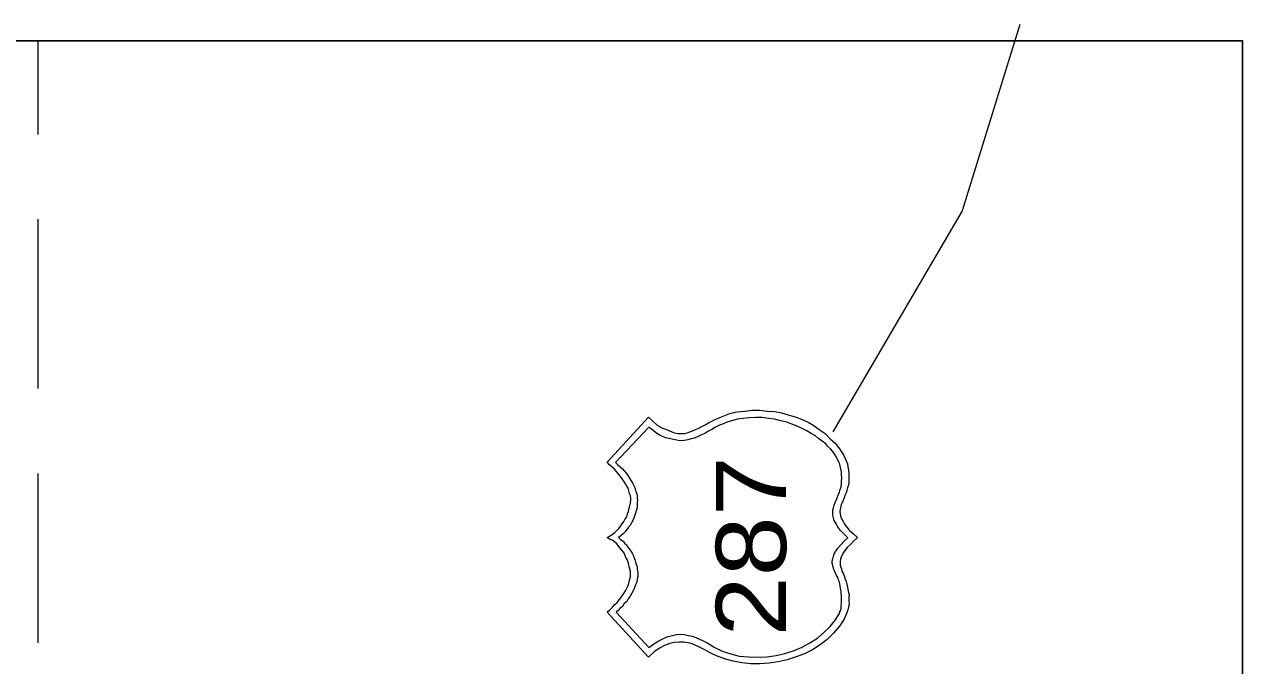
# Model space of a CAD drawing. Extents: x 2363323 to 2367082, y 6956018 to 6980837.
# Drawn here: x 2366130.8 to 2366219.2, y 6980790.2 to 6980836.7 of the extents above; entities that cross this region are included whole.
import ezdxf

# ---------------------------------------------------------------- set-up
doc = ezdxf.new("R2010")
doc.units = 0
doc.header["$LTSCALE"] = 4.1
doc.linetypes.add('MEDIUM_DASHED', pattern=[4.5, 3, -1.5])
doc.layers.add('62', color=7, linetype='Continuous', lineweight=13)
doc.layers.add('63', color=7, linetype='Continuous', lineweight=13)

msp = doc.modelspace()

# ---------------------------------------------------------------- linework, layer by layer
at = {"layer": '62'}
for p, q in [((2366203.073, 6980836.74), (2366198.884, 6980823.214)), ((2366198.884, 6980823.214), (2366189.502, 6980807.17))]:
    msp.add_line(p, q, dxfattribs=at)
at = {"layer": '62', "linetype": 'MEDIUM_DASHED'}
msp.add_line((2366131.806, 6980385.954), (2366131.805, 6980835.548), dxfattribs=at)
at = {"layer": '62', "lineweight": 25}
msp.add_lwpolyline([(2365753.976, 6980385.954), (2366219.249, 6980385.954), (2366219.249, 6980835.546), (2365753.974, 6980835.546)], dxfattribs=at)
at = {"layer": '62'}
for points in [[(2366176.114, 6980790.813), (2366173.121, 6980794.074), (2366173.301, 6980794.256), (2366173.504, 6980794.434), (2366173.661, 6980794.636), (2366173.842, 6980794.794), (2366173.998, 6980795), (2366174.135, 6980795.178), (2366174.268, 6980795.358), (2366174.404, 6980795.56), (2366174.495, 6980795.718), (2366174.584, 6980795.92), (2366174.675, 6980796.1), (2366174.72, 6980796.303), (2366174.765, 6980796.483), (2366174.807, 6980796.64), (2366174.81, 6980796.866), (2366174.81, 6980797.068), (2366174.764, 6980797.203), (2366174.718, 6980797.36), (2366174.696, 6980797.54), (2366174.628, 6980797.719), (2366174.561, 6980797.902), (2366174.471, 6980798.058), (2366174.404, 6980798.24), (2366174.315, 6980798.418), (2366174.18, 6980798.576), (2366174.045, 6980798.756), (2366173.91, 6980798.913), (2366173.798, 6980799.07), (2366173.638, 6980799.183), (2366173.482, 6980799.318), (2366173.28, 6980799.386), (2366173.122, 6980799.498), (2366173.278, 6980799.61), (2366173.481, 6980799.723), (2366173.661, 6980799.858), (2366173.798, 6980799.993), (2366173.955, 6980800.152), (2366174.09, 6980800.33), (2366174.201, 6980800.488), (2366174.315, 6980800.668), (2366174.426, 6980800.846), (2366174.538, 6980801.006), (2366174.585, 6980801.23), (2366174.674, 6980801.39), (2366174.72, 6980801.636), (2366174.764, 6980801.793), (2366174.81, 6980802.018), (2366174.832, 6980802.2), (2366174.831, 6980802.356), (2366174.808, 6980802.558), (2366174.742, 6980802.693), (2366174.698, 6980802.894), (2366174.628, 6980803.076), (2366174.538, 6980803.234), (2366174.45, 6980803.392), (2366174.336, 6980803.593), (2366174.201, 6980803.752), (2366174.09, 6980803.93), (2366173.931, 6980804.088), (2366173.796, 6980804.29), (2366173.64, 6980804.45), (2366173.458, 6980804.628), (2366173.278, 6980804.786), (2366173.121, 6980804.966), (2366176.114, 6980808.23), (2366176.43, 6980807.936), (2366176.744, 6980807.644), (2366177.126, 6980807.44), (2366177.531, 6980807.284), (2366177.915, 6980807.126), (2366178.252, 6980807.056), (2366178.544, 6980807.058), (2366178.746, 6980807.058), (2366178.928, 6980807.103), (2366179.128, 6980807.172), (2366179.31, 6980807.238), (2366179.534, 6980807.328), (2366179.758, 6980807.44), (2366179.984, 6980807.553), (2366180.231, 6980807.69), (2366180.478, 6980807.823), (2366180.75, 6980807.958), (2366180.996, 6980808.093), (2366181.29, 6980808.206), (2366181.538, 6980808.318), (2366181.785, 6980808.408), (2366182.031, 6980808.498), (2366182.302, 6980808.566), (2366182.548, 6980808.61), (2366183.112, 6980808.678), (2366183.675, 6980808.747), (2366184.192, 6980808.746), (2366184.731, 6980808.678), (2366185.271, 6980808.634), (2366185.768, 6980808.543), (2366186.262, 6980808.408), (2366186.756, 6980808.25), (2366187.228, 6980808.093), (2366187.702, 6980807.868)], [(2366188.466, 6980806.676), (2366188.242, 6980806.878), (2366187.926, 6980807.06), (2366187.612, 6980807.238), (2366187.274, 6980807.418), (2366186.915, 6980807.576), (2366186.532, 6980807.734), (2366186.15, 6980807.87), (2366185.721, 6980807.98), (2366185.272, 6980808.093), (2366184.844, 6980808.138), (2366184.372, 6980808.204), (2366183.898, 6980808.207), (2366183.405, 6980808.183), (2366182.976, 6980808.138), (2366182.572, 6980808.093), (2366182.235, 6980807.982), (2366181.875, 6980807.89), (2366181.558, 6980807.756), (2366181.266, 6980807.643), (2366180.974, 6980807.508), (2366180.705, 6980807.35), (2366180.434, 6980807.194), (2366180.208, 6980807.058), (2366179.961, 6980806.946), (2366179.714, 6980806.833), (2366179.445, 6980806.72), (2366179.22, 6980806.653), (2366178.971, 6980806.586), (2366178.701, 6980806.54), (2366178.386, 6980806.518), (2366178.048, 6980806.586), (2366177.711, 6980806.653), (2366177.374, 6980806.743), (2366177.015, 6980806.878), (2366176.721, 6980807.058), (2366176.428, 6980807.284), (2366176.136, 6980807.508), (2366173.728, 6980804.943), (2366173.886, 6980804.787), (2366174.045, 6980804.65), (2366174.224, 6980804.493), (2366174.36, 6980804.336), (2366174.516, 6980804.157), (2366174.628, 6980803.976), (2366174.741, 6980803.797), (2366174.854, 6980803.616), (2366174.966, 6980803.413), (2366175.078, 6980803.233), (2366175.146, 6980803.03), (2366175.191, 6980802.852), (2366175.26, 6980802.67), (2366175.281, 6980802.513), (2366175.304, 6980802.357), (2366175.328, 6980802.198), (2366175.304, 6980802.042), (2366175.281, 6980801.86), (2366175.282, 6980801.66), (2366175.236, 6980801.5), (2366175.168, 6980801.276), (2366175.124, 6980801.118), (2366175.056, 6980800.938), (2366174.968, 6980800.736), (2366174.876, 6980800.578), (2366174.786, 6980800.376), (2366174.675, 6980800.242), (2366174.538, 6980800.083), (2366174.426, 6980799.904), (2366174.268, 6980799.77), (2366174.112, 6980799.634), (2366173.931, 6980799.5), (2366174.088, 6980799.363), (2366174.268, 6980799.23), (2366174.381, 6980799.093), (2366174.516, 6980798.958), (2366174.606, 6980798.802), (2366174.718, 6980798.688), (2366174.832, 6980798.508), (2366174.921, 6980798.373), (2366174.99, 6980798.216), (2366175.08, 6980798.036), (2366175.125, 6980797.9), (2366175.168, 6980797.722), (2366175.214, 6980797.563), (2366175.282, 6980797.406), (2366175.281, 6980797.226), (2366175.326, 6980797.07), (2366175.35, 6980796.91), (2366175.348, 6980796.686), (2366175.281, 6980796.483), (2366175.258, 6980796.258), (2366175.168, 6980796.078), (2366175.102, 6980795.852), (2366175.011, 6980795.63), (2366174.898, 6980795.47), (2366174.786, 6980795.246), (2366174.651, 6980795.043), (2366174.538, 6980794.863), (2366174.357, 6980794.704), (2366174.224, 6980794.503), (2366174.044, 6980794.344)], [(2366187.702, 6980807.868), (2366188.128, 6980807.62), (2366188.511, 6980807.328), (2366188.94, 6980807.058), (2366189.298, 6980806.674), (2366189.66, 6980806.338), (2366189.975, 6980805.933), (2366190.132, 6980805.708), (2366190.266, 6980805.507), (2366190.378, 6980805.28), (2366190.468, 6980805.056), (2366190.56, 6980804.853), (2366190.581, 6980804.628), (2366190.628, 6980804.38), (2366190.671, 6980804.18), (2366190.671, 6980803.93), (2366190.671, 6980803.704), (2366190.648, 6980803.503), (2366190.626, 6980803.323), (2366190.558, 6980803.1), (2366190.514, 6980802.918), (2366190.47, 6980802.738), (2366190.378, 6980802.558), (2366190.311, 6980802.38), (2366190.245, 6980802.198), (2366190.176, 6980802.063), (2366190.11, 6980801.883), (2366190.086, 6980801.748), (2366190.041, 6980801.568), (2366189.996, 6980801.39), (2366190.02, 6980801.23), (2366190.065, 6980801.05), (2366190.131, 6980800.848), (2366190.244, 6980800.668), (2366190.356, 6980800.466), (2366190.514, 6980800.24), (2366190.716, 6980800.016), (2366190.986, 6980799.768), (2366191.278, 6980799.498), (2366191.008, 6980799.226), (2366190.784, 6980799.003), (2366190.558, 6980798.8), (2366190.401, 6980798.576), (2366190.268, 6980798.418), (2366190.178, 6980798.238), (2366190.108, 6980798.08), (2366190.065, 6980797.923), (2366190.041, 6980797.788), (2366190.042, 6980797.63), (2366190.042, 6980797.496), (2366190.086, 6980797.34), (2366190.131, 6980797.227), (2366190.154, 6980797.068), (2366190.244, 6980796.912), (2366190.288, 6980796.776), (2366190.356, 6980796.642), (2366190.402, 6980796.483), (2366190.468, 6980796.303), (2366190.514, 6980796.1), (2366190.558, 6980795.92), (2366190.581, 6980795.718), (2366190.628, 6980795.516), (2366190.672, 6980795.337), (2366190.671, 6980795.112), (2366190.671, 6980794.908), (2366190.672, 6980794.704), (2366190.628, 6980794.458), (2366190.582, 6980794.254), (2366190.514, 6980794.029), (2366190.424, 6980793.806), (2366190.311, 6980793.579), (2366189.974, 6980793.062), (2366189.546, 6980792.565), (2366189.096, 6980792.094), (2366188.578, 6980791.712), (2366188.018, 6980791.352), (2366187.431, 6980791.06), (2366186.824, 6980790.836), (2366186.171, 6980790.632), (2366185.52, 6980790.474), (2366184.866, 6980790.384), (2366184.191, 6980790.339), (2366183.538, 6980790.338), (2366182.884, 6980790.406), (2366182.258, 6980790.519), (2366181.626, 6980790.699), (2366181.064, 6980790.924), (2366180.838, 6980791.014), (2366180.591, 6980791.126), (2366180.366, 6980791.262), (2366180.098, 6980791.396), (2366179.828, 6980791.533), (2366179.558, 6980791.666), (2366179.286, 6980791.78), (2366178.995, 6980791.846), (2366178.68, 6980791.914), (2366178.341, 6980791.916), (2366178.005, 6980791.892), (2366177.666, 6980791.802), (2366177.284, 6980791.668), (2366176.902, 6980791.464)], [(2366173.774, 6980794.076), (2366176.136, 6980791.509), (2366176.498, 6980791.779), (2366176.858, 6980792.004), (2366177.194, 6980792.162), (2366177.508, 6980792.319), (2366177.846, 6980792.386), (2366178.138, 6980792.454), (2366178.408, 6980792.476), (2366178.724, 6980792.456), (2366179.018, 6980792.388), (2366179.286, 6980792.342), (2366179.558, 6980792.252), (2366179.828, 6980792.116), (2366180.096, 6980792.006), (2366180.366, 6980791.869), (2366180.615, 6980791.713), (2366180.884, 6980791.554), (2366181.468, 6980791.262), (2366182.1, 6980791.06), (2366182.706, 6980790.902), (2366183.381, 6980790.834), (2366184.034, 6980790.812), (2366184.708, 6980790.834), (2366185.384, 6980790.946), (2366186.014, 6980791.082), (2366186.644, 6980791.284), (2366187.274, 6980791.554), (2366187.838, 6980791.869), (2366188.378, 6980792.208), (2366188.848, 6980792.612), (2366189.298, 6980793.039), (2366189.66, 6980793.512), (2366189.974, 6980793.984), (2366190.018, 6980794.096), (2366190.088, 6980794.232), (2366190.108, 6980794.389), (2366190.108, 6980794.569), (2366190.131, 6980794.704), (2366190.132, 6980794.886), (2366190.132, 6980795.066), (2366190.132, 6980795.246), (2366190.11, 6980795.448), (2366190.108, 6980795.606), (2366190.065, 6980795.806), (2366190.041, 6980795.988), (2366189.998, 6980796.146), (2366189.952, 6980796.326), (2366189.884, 6980796.483), (2366189.861, 6980796.618), (2366189.772, 6980796.753), (2366189.702, 6980796.91), (2366189.638, 6980797.023), (2366189.568, 6980797.179), (2366189.524, 6980797.338), (2366189.502, 6980797.473), (2366189.458, 6980797.63), (2366189.456, 6980797.788), (2366189.501, 6980797.946), (2366189.546, 6980798.15), (2366189.591, 6980798.328), (2366189.726, 6980798.506), (2366189.861, 6980798.734), (2366190.086, 6980798.958), (2366190.311, 6980799.228), (2366190.582, 6980799.476), (2366190.288, 6980799.768), (2366190.041, 6980800.038), (2366189.862, 6980800.284), (2366189.704, 6980800.533), (2366189.591, 6980800.736), (2366189.546, 6980800.938), (2366189.501, 6980801.118), (2366189.501, 6980801.343), (2366189.501, 6980801.502), (2366189.546, 6980801.658), (2366189.591, 6980801.86), (2366189.658, 6980802.04), (2366189.748, 6980802.2), (2366189.814, 6980802.378), (2366189.885, 6980802.58), (2366189.975, 6980802.783), (2366190.042, 6980802.986), (2366190.108, 6980803.186), (2366190.132, 6980803.39), (2366190.131, 6980803.616), (2366190.154, 6980803.82), (2366190.132, 6980804.044), (2366190.131, 6980804.246), (2366190.086, 6980804.469), (2366190.042, 6980804.696), (2366189.974, 6980804.898), (2366189.862, 6980805.124), (2366189.771, 6980805.326), (2366189.636, 6980805.528), (2366189.502, 6980805.753), (2366189.321, 6980805.933), (2366189.118, 6980806.136), (2366188.962, 6980806.316), (2366188.714, 6980806.496), (2366188.466, 6980806.676)], [(2366174.044, 6980794.344), (2366173.91, 6980794.209), (2366173.774, 6980794.076)], [(2366176.902, 6980791.464), (2366176.52, 6980791.194), (2366176.114, 6980790.813)]]:
    msp.add_lwpolyline(points, dxfattribs=at)
at = {"layer": '63'}
for p, q in [((2366203.073, 6980836.74), (2366198.884, 6980823.214)), ((2366198.884, 6980823.214), (2366189.502, 6980807.17))]:
    msp.add_line(p, q, dxfattribs=at)
at = {"layer": '63', "linetype": 'MEDIUM_DASHED'}
msp.add_line((2366131.806, 6980385.954), (2366131.805, 6980835.548), dxfattribs=at)
at = {"layer": '63', "lineweight": 25}
msp.add_lwpolyline([(2365753.976, 6980385.954), (2366219.249, 6980385.954), (2366219.249, 6980835.546), (2365753.974, 6980835.546)], dxfattribs=at)
at = {"layer": '63'}
for points in [[(2366176.114, 6980790.813), (2366173.121, 6980794.074), (2366173.301, 6980794.256), (2366173.504, 6980794.434), (2366173.661, 6980794.636), (2366173.842, 6980794.794), (2366173.998, 6980795), (2366174.135, 6980795.178), (2366174.268, 6980795.358), (2366174.404, 6980795.56), (2366174.495, 6980795.718), (2366174.584, 6980795.92), (2366174.675, 6980796.1), (2366174.72, 6980796.303), (2366174.765, 6980796.483), (2366174.807, 6980796.64), (2366174.81, 6980796.866), (2366174.81, 6980797.068), (2366174.764, 6980797.203), (2366174.718, 6980797.36), (2366174.696, 6980797.54), (2366174.628, 6980797.719), (2366174.561, 6980797.902), (2366174.471, 6980798.058), (2366174.404, 6980798.24), (2366174.315, 6980798.418), (2366174.18, 6980798.576), (2366174.045, 6980798.756), (2366173.91, 6980798.913), (2366173.798, 6980799.07), (2366173.638, 6980799.183), (2366173.482, 6980799.318), (2366173.28, 6980799.386), (2366173.122, 6980799.498), (2366173.278, 6980799.61), (2366173.481, 6980799.723), (2366173.661, 6980799.858), (2366173.798, 6980799.993), (2366173.955, 6980800.152), (2366174.09, 6980800.33), (2366174.201, 6980800.488), (2366174.315, 6980800.668), (2366174.426, 6980800.846), (2366174.538, 6980801.006), (2366174.585, 6980801.23), (2366174.674, 6980801.39), (2366174.72, 6980801.636), (2366174.764, 6980801.793), (2366174.81, 6980802.018), (2366174.832, 6980802.2), (2366174.831, 6980802.356), (2366174.808, 6980802.558), (2366174.742, 6980802.693), (2366174.698, 6980802.894), (2366174.628, 6980803.076), (2366174.538, 6980803.234), (2366174.45, 6980803.392), (2366174.336, 6980803.593), (2366174.201, 6980803.752), (2366174.09, 6980803.93), (2366173.931, 6980804.088), (2366173.796, 6980804.29), (2366173.64, 6980804.45), (2366173.458, 6980804.628), (2366173.278, 6980804.786), (2366173.121, 6980804.966), (2366176.114, 6980808.23), (2366176.43, 6980807.936), (2366176.744, 6980807.644), (2366177.126, 6980807.44), (2366177.531, 6980807.284), (2366177.915, 6980807.126), (2366178.252, 6980807.056), (2366178.544, 6980807.058), (2366178.746, 6980807.058), (2366178.928, 6980807.103), (2366179.128, 6980807.172), (2366179.31, 6980807.238), (2366179.534, 6980807.328), (2366179.758, 6980807.44), (2366179.984, 6980807.553), (2366180.231, 6980807.69), (2366180.478, 6980807.823), (2366180.75, 6980807.958), (2366180.996, 6980808.093), (2366181.29, 6980808.206), (2366181.538, 6980808.318), (2366181.785, 6980808.408), (2366182.031, 6980808.498), (2366182.302, 6980808.566), (2366182.548, 6980808.61), (2366183.112, 6980808.678), (2366183.675, 6980808.747), (2366184.192, 6980808.746), (2366184.731, 6980808.678), (2366185.271, 6980808.634), (2366185.768, 6980808.543), (2366186.262, 6980808.408), (2366186.756, 6980808.25), (2366187.228, 6980808.093), (2366187.702, 6980807.868)], [(2366188.466, 6980806.676), (2366188.242, 6980806.878), (2366187.926, 6980807.06), (2366187.612, 6980807.238), (2366187.274, 6980807.418), (2366186.915, 6980807.576), (2366186.532, 6980807.734), (2366186.15, 6980807.87), (2366185.721, 6980807.98), (2366185.272, 6980808.093), (2366184.844, 6980808.138), (2366184.372, 6980808.204), (2366183.898, 6980808.207), (2366183.405, 6980808.183), (2366182.976, 6980808.138), (2366182.572, 6980808.093), (2366182.235, 6980807.982), (2366181.875, 6980807.89), (2366181.558, 6980807.756), (2366181.266, 6980807.643), (2366180.974, 6980807.508), (2366180.705, 6980807.35), (2366180.434, 6980807.194), (2366180.208, 6980807.058), (2366179.961, 6980806.946), (2366179.714, 6980806.833), (2366179.445, 6980806.72), (2366179.22, 6980806.653), (2366178.971, 6980806.586), (2366178.701, 6980806.54), (2366178.386, 6980806.518), (2366178.048, 6980806.586), (2366177.711, 6980806.653), (2366177.374, 6980806.743), (2366177.015, 6980806.878), (2366176.721, 6980807.058), (2366176.428, 6980807.284), (2366176.136, 6980807.508), (2366173.728, 6980804.943), (2366173.886, 6980804.787), (2366174.045, 6980804.65), (2366174.224, 6980804.493), (2366174.36, 6980804.336), (2366174.516, 6980804.157), (2366174.628, 6980803.976), (2366174.741, 6980803.797), (2366174.854, 6980803.616), (2366174.966, 6980803.413), (2366175.078, 6980803.233), (2366175.146, 6980803.03), (2366175.191, 6980802.852), (2366175.26, 6980802.67), (2366175.281, 6980802.513), (2366175.304, 6980802.357), (2366175.328, 6980802.198), (2366175.304, 6980802.042), (2366175.281, 6980801.86), (2366175.282, 6980801.66), (2366175.236, 6980801.5), (2366175.168, 6980801.276), (2366175.124, 6980801.118), (2366175.056, 6980800.938), (2366174.968, 6980800.736), (2366174.876, 6980800.578), (2366174.786, 6980800.376), (2366174.675, 6980800.242), (2366174.538, 6980800.083), (2366174.426, 6980799.904), (2366174.268, 6980799.77), (2366174.112, 6980799.634), (2366173.931, 6980799.5), (2366174.088, 6980799.363), (2366174.268, 6980799.23), (2366174.381, 6980799.093), (2366174.516, 6980798.958), (2366174.606, 6980798.802), (2366174.718, 6980798.688), (2366174.832, 6980798.508), (2366174.921, 6980798.373), (2366174.99, 6980798.216), (2366175.08, 6980798.036), (2366175.125, 6980797.9), (2366175.168, 6980797.722), (2366175.214, 6980797.563), (2366175.282, 6980797.406), (2366175.281, 6980797.226), (2366175.326, 6980797.07), (2366175.35, 6980796.91), (2366175.348, 6980796.686), (2366175.281, 6980796.483), (2366175.258, 6980796.258), (2366175.168, 6980796.078), (2366175.102, 6980795.852), (2366175.011, 6980795.63), (2366174.898, 6980795.47), (2366174.786, 6980795.246), (2366174.651, 6980795.043), (2366174.538, 6980794.863), (2366174.357, 6980794.704), (2366174.224, 6980794.503), (2366174.044, 6980794.344)], [(2366187.702, 6980807.868), (2366188.128, 6980807.62), (2366188.511, 6980807.328), (2366188.94, 6980807.058), (2366189.298, 6980806.674), (2366189.66, 6980806.338), (2366189.975, 6980805.933), (2366190.132, 6980805.708), (2366190.266, 6980805.507), (2366190.378, 6980805.28), (2366190.468, 6980805.056), (2366190.56, 6980804.853), (2366190.581, 6980804.628), (2366190.628, 6980804.38), (2366190.671, 6980804.18), (2366190.671, 6980803.93), (2366190.671, 6980803.704), (2366190.648, 6980803.503), (2366190.626, 6980803.323), (2366190.558, 6980803.1), (2366190.514, 6980802.918), (2366190.47, 6980802.738), (2366190.378, 6980802.558), (2366190.311, 6980802.38), (2366190.245, 6980802.198), (2366190.176, 6980802.063), (2366190.11, 6980801.883), (2366190.086, 6980801.748), (2366190.041, 6980801.568), (2366189.996, 6980801.39), (2366190.02, 6980801.23), (2366190.065, 6980801.05), (2366190.131, 6980800.848), (2366190.244, 6980800.668), (2366190.356, 6980800.466), (2366190.514, 6980800.24), (2366190.716, 6980800.016), (2366190.986, 6980799.768), (2366191.278, 6980799.498), (2366191.008, 6980799.226), (2366190.784, 6980799.003), (2366190.558, 6980798.8), (2366190.401, 6980798.576), (2366190.268, 6980798.418), (2366190.178, 6980798.238), (2366190.108, 6980798.08), (2366190.065, 6980797.923), (2366190.041, 6980797.788), (2366190.042, 6980797.63), (2366190.042, 6980797.496), (2366190.086, 6980797.34), (2366190.131, 6980797.227), (2366190.154, 6980797.068), (2366190.244, 6980796.912), (2366190.288, 6980796.776), (2366190.356, 6980796.642), (2366190.402, 6980796.483), (2366190.468, 6980796.303), (2366190.514, 6980796.1), (2366190.558, 6980795.92), (2366190.581, 6980795.718), (2366190.628, 6980795.516), (2366190.672, 6980795.337), (2366190.671, 6980795.112), (2366190.671, 6980794.908), (2366190.672, 6980794.704), (2366190.628, 6980794.458), (2366190.582, 6980794.254), (2366190.514, 6980794.029), (2366190.424, 6980793.806), (2366190.311, 6980793.579), (2366189.974, 6980793.062), (2366189.546, 6980792.565), (2366189.096, 6980792.094), (2366188.578, 6980791.712), (2366188.018, 6980791.352), (2366187.431, 6980791.06), (2366186.824, 6980790.836), (2366186.171, 6980790.632), (2366185.52, 6980790.474), (2366184.866, 6980790.384), (2366184.191, 6980790.339), (2366183.538, 6980790.338), (2366182.884, 6980790.406), (2366182.258, 6980790.519), (2366181.626, 6980790.699), (2366181.064, 6980790.924), (2366180.838, 6980791.014), (2366180.591, 6980791.126), (2366180.366, 6980791.262), (2366180.098, 6980791.396), (2366179.828, 6980791.533), (2366179.558, 6980791.666), (2366179.286, 6980791.78), (2366178.995, 6980791.846), (2366178.68, 6980791.914), (2366178.341, 6980791.916), (2366178.005, 6980791.892), (2366177.666, 6980791.802), (2366177.284, 6980791.668), (2366176.902, 6980791.464)], [(2366173.774, 6980794.076), (2366176.136, 6980791.509), (2366176.498, 6980791.779), (2366176.858, 6980792.004), (2366177.194, 6980792.162), (2366177.508, 6980792.319), (2366177.846, 6980792.386), (2366178.138, 6980792.454), (2366178.408, 6980792.476), (2366178.724, 6980792.456), (2366179.018, 6980792.388), (2366179.286, 6980792.342), (2366179.558, 6980792.252), (2366179.828, 6980792.116), (2366180.096, 6980792.006), (2366180.366, 6980791.869), (2366180.615, 6980791.713), (2366180.884, 6980791.554), (2366181.468, 6980791.262), (2366182.1, 6980791.06), (2366182.706, 6980790.902), (2366183.381, 6980790.834), (2366184.034, 6980790.812), (2366184.708, 6980790.834), (2366185.384, 6980790.946), (2366186.014, 6980791.082), (2366186.644, 6980791.284), (2366187.274, 6980791.554), (2366187.838, 6980791.869), (2366188.378, 6980792.208), (2366188.848, 6980792.612), (2366189.298, 6980793.039), (2366189.66, 6980793.512), (2366189.974, 6980793.984), (2366190.018, 6980794.096), (2366190.088, 6980794.232), (2366190.108, 6980794.389), (2366190.108, 6980794.569), (2366190.131, 6980794.704), (2366190.132, 6980794.886), (2366190.132, 6980795.066), (2366190.132, 6980795.246), (2366190.11, 6980795.448), (2366190.108, 6980795.606), (2366190.065, 6980795.806), (2366190.041, 6980795.988), (2366189.998, 6980796.146), (2366189.952, 6980796.326), (2366189.884, 6980796.483), (2366189.861, 6980796.618), (2366189.772, 6980796.753), (2366189.702, 6980796.91), (2366189.638, 6980797.023), (2366189.568, 6980797.179), (2366189.524, 6980797.338), (2366189.502, 6980797.473), (2366189.458, 6980797.63), (2366189.456, 6980797.788), (2366189.501, 6980797.946), (2366189.546, 6980798.15), (2366189.591, 6980798.328), (2366189.726, 6980798.506), (2366189.861, 6980798.734), (2366190.086, 6980798.958), (2366190.311, 6980799.228), (2366190.582, 6980799.476), (2366190.288, 6980799.768), (2366190.041, 6980800.038), (2366189.862, 6980800.284), (2366189.704, 6980800.533), (2366189.591, 6980800.736), (2366189.546, 6980800.938), (2366189.501, 6980801.118), (2366189.501, 6980801.343), (2366189.501, 6980801.502), (2366189.546, 6980801.658), (2366189.591, 6980801.86), (2366189.658, 6980802.04), (2366189.748, 6980802.2), (2366189.814, 6980802.378), (2366189.885, 6980802.58), (2366189.975, 6980802.783), (2366190.042, 6980802.986), (2366190.108, 6980803.186), (2366190.132, 6980803.39), (2366190.131, 6980803.616), (2366190.154, 6980803.82), (2366190.132, 6980804.044), (2366190.131, 6980804.246), (2366190.086, 6980804.469), (2366190.042, 6980804.696), (2366189.974, 6980804.898), (2366189.862, 6980805.124), (2366189.771, 6980805.326), (2366189.636, 6980805.528), (2366189.502, 6980805.753), (2366189.321, 6980805.933), (2366189.118, 6980806.136), (2366188.962, 6980806.316), (2366188.714, 6980806.496), (2366188.466, 6980806.676)], [(2366174.044, 6980794.344), (2366173.91, 6980794.209), (2366173.774, 6980794.076)], [(2366176.902, 6980791.464), (2366176.52, 6980791.194), (2366176.114, 6980790.813)]]:
    msp.add_lwpolyline(points, dxfattribs=at)

# ---------------------------------------------------------------- texts
at = {"layer": '62', "width": 1.15}
msp.add_text('287', height=5.099, rotation=90, dxfattribs=at).set_placement((2366186.103, 6980792.319))
at = {"layer": '63', "width": 1.15}
msp.add_text('287', height=5.099, rotation=90, dxfattribs=at).set_placement((2366186.103, 6980792.319))

doc.saveas('drawing.dxf')
